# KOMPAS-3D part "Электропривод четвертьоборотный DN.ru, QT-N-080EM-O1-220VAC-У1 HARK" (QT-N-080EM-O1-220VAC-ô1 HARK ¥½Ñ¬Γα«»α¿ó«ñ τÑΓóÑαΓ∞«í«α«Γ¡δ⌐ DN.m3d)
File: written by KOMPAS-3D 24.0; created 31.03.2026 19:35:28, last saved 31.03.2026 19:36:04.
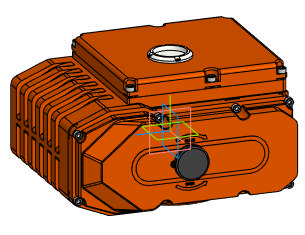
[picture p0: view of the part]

Document properties: Автор: DN.RU; Полное имя файла: D:\PROJECT CAD\DN.RU\...195\Исходники\220В\QT-N-080EM-O1-220VAC-У1 HARK Электропривод четвертьоборотный DN.ru\QT-N-080EM-O1-220VAC-У1 HARK Электропривод четвертьоборотный DN.m3d

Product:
- Body: Твердое тело1  | qty 1
    Масса: 62.544949
- Part/product: Электропривод четвертьоборотный DN.ru  | designation QT-N-080EM-O1-220VAC-У1 HARK
    Масса: 14.3
    Раздел спецификации: Прочие изделия
    Комментарий: D300-14490
    Примечание: D300-14489
    additional columns: Сталь

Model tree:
1. Твердое тело1  (labels: Твердое тело1)

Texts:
  QT-N-080EM-O1-220VAC-У1 HARK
